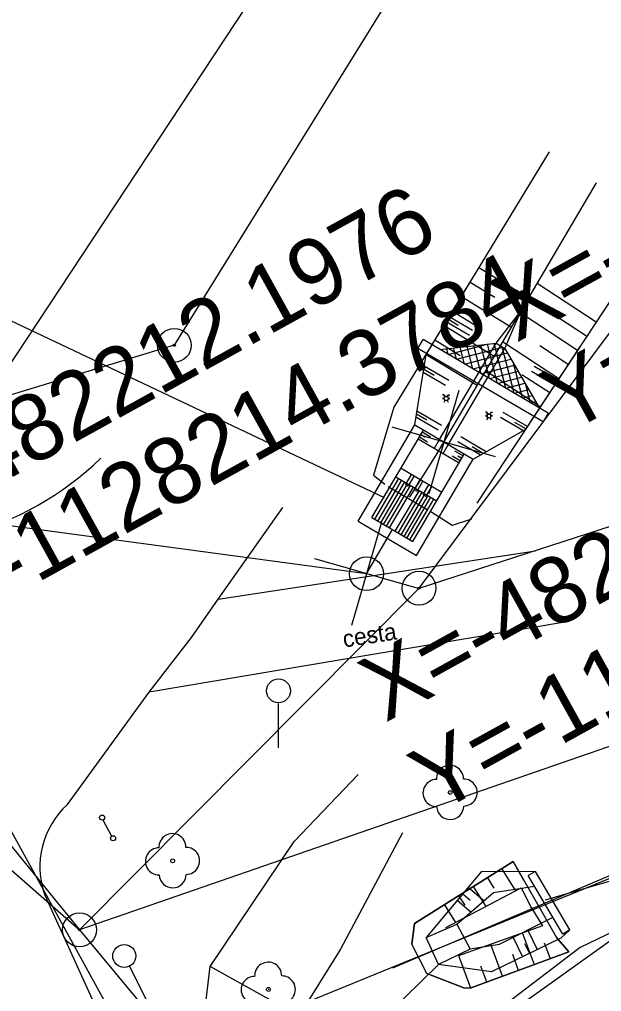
# Model space of a CAD drawing. Extents: x -483721 to -481876, y -1129170 to -1127366.
# Drawn here: x -482206.61 to -482189.41, y -1128228.85 to -1128200.12 of the extents above; entities that cross this region are included whole.
import ezdxf

# ---------------------------------------------------------------- set-up
doc = ezdxf.new("R2010")
doc.units = 0
for name, color, linetype in [('Hranice parcel', 7, 'Continuous'), ('kresba', 7, 'Continuous'), ('SO 01', 7, 'Continuous'), ('STROM', 7, 'Continuous'), ('u_HV', 7, 'Continuous'), ('u_vytyčení', 7, 'Continuous'), ('vzorák', 7, 'Continuous'), ('Značky bodu BP', 7, 'Continuous'), ('ˇ12', 7, 'Continuous'), ('ˇ8', 7, 'Continuous')]:
    doc.layers.add(name, color=color, linetype=linetype)

# ---------------------------------------------------------------- blocks, each defined once
blk = doc.blocks.new('STROM')
blk.add_circle((0, 0), 0.143)
for centre, start, end in [((-0.019, 1.012), 359.33392, 182.80997), ((-1.012, -0.037), 90.28964, 270.7727), ((0.994, 0), 270.35705, 90.71965), ((-1.012, -0.037), 2.55394, 2.80997), ((-0.019, 1.012), 270.28964, 270.71965), ((0, -0.993), 90.35705, 90.7727), ((0.994, 0), 179.33392, 179.58937), ((0, -0.993), 182.55394, 359.58937)]:
    blk.add_arc(centre, 1, start, end)

msp = doc.modelspace()

# ---------------------------------------------------------------- linework, layer by layer
at = {"layer": 'Hranice parcel'}
for p, q in [((-482132.99, -1128202.16), (-482204.83, -1128227.03)), ((-482194.8, -1128216.93), (-482167.83, -1128208.16)), ((-482204.83, -1128227.03), (-482194.8, -1128216.93)), ((-482213.95, -1128219.04), (-482204.83, -1128227.03)), ((-482198.83, -1128234.26), (-482186.92, -1128225.75)), ((-482204.83, -1128227.03), (-482198.83, -1128234.26))]:
    msp.add_line(p, q, dxfattribs=at)
for points in [[(-482194.8, -1128216.93), (-482149.76, -1128156.56), (-482131.701, -1128127.511)], [(-482164.86, -1128146.61), (-482163.44, -1128147.46), (-482202.03, -1128209.75), (-482210.32, -1128212.27)], [(-482228.12, -1128175.02), (-482207.37, -1128211.05), (-482169.26, -1128153.28)], [(-482214.43, -1128213.98), (-482210.05, -1128220.62), (-482205.48, -1128226.23), (-482204.83, -1128227.03)]]:
    msp.add_lwpolyline(points, dxfattribs=at)
at = {"layer": 'kresba'}
for p, q in [((-482200.73, -1128217.25), (-482198.82, -1128214.544)), ((-482200.73, -1128217.25), (-482191.36, -1128215.83)), ((-482201.52, -1128218.39), (-482200.73, -1128217.25)), ((-482190.49, -1128217.93), (-482202.77, -1128220)), ((-482202.77, -1128220), (-482201.52, -1128218.39)), ((-482205.19, -1128223.32), (-482202.77, -1128220)), ((-482198.95, -1128221.65), (-482198.95, -1128220.336)), ((-482198.49, -1128224.42), (-482196.6, -1128222.44)), ((-482204.138, -1128223.781), (-482203.882, -1128224.259)), ((-482195.29, -1128224.16), (-482197.12, -1128227.6)), ((-482200.97, -1128228.11), (-482198.49, -1128224.42)), ((-482187.18, -1128225.01), (-482191.07, -1128226.15)), ((-482184.556, -1128224.904), (-482190.04, -1128227.55)), ((-482192.96, -1128225.31), (-482194.59, -1128227.25)), ((-482191.36, -1128225.3), (-482192.96, -1128225.31)), ((-482191.36, -1128225.3), (-482191.575, -1128225.427)), ((-482190.34, -1128227.03), (-482191.36, -1128225.3)), ((-482190.555, -1128227.157), (-482191.575, -1128225.427)), ((-482192.885, -1128226.168), (-482193.352, -1128225.776)), ((-482192.6, -1128225.92), (-482191.393, -1128225.736)), ((-482205.86, -1128226), (-482203.7, -1128230.73)), ((-482193.68, -1128226.86), (-482192.6, -1128225.92)), ((-482193.272, -1128226.505), (-482193.678, -1128226.164)), ((-482193.285, -1128226.161), (-482193.513, -1128225.969)), ((-482190.846, -1128226.665), (-482192.43, -1128227.46)), ((-482194.59, -1128227.25), (-482193.68, -1128226.86)), ((-482193.68, -1128226.86), (-482193.29, -1128227.6)), ((-482191.588, -1128227.037), (-482191.308, -1128227.611)), ((-482190.34, -1128227.03), (-482190.61, -1128227.27)), ((-482190.34, -1128227.03), (-482190.555, -1128227.157)), ((-482194.226, -1128228.049), (-482194.59, -1128227.25)), ((-482190.61, -1128227.27), (-482192.66, -1128228.27)), ((-482192.022, -1128227.255), (-482191.744, -1128227.823)), ((-482190.04, -1128227.55), (-482198.56, -1128234.04)), ((-482197.12, -1128227.6), (-482198.35, -1128229.57)), ((-482193.29, -1128227.6), (-482194.226, -1128228.049)), ((-482192.43, -1128227.46), (-482193.29, -1128227.6)), ((-482191.68, -1128227.434), (-482191.539, -1128227.723)), ((-482203.352, -1128228.1), (-482202.46, -1128229.9)), ((-482201.28, -1128230.72), (-482200.97, -1128228.11)), ((-482198.35, -1128229.57), (-482200.97, -1128228.11)), ((-482196.73, -1128230.5), (-482194.226, -1128228.049)), ((-482192.66, -1128228.27), (-482194.226, -1128228.049))]:
    msp.add_line(p, q, dxfattribs=at)
for centre, radius in [((-482198.953, -1128219.963), 0.352), ((-482204.166, -1128223.711), 0.0752), ((-482203.841, -1128224.323), 0.0752), ((-482203.51, -1128227.8), 0.339)]:
    msp.add_circle(centre, radius, dxfattribs=at)
for centre, radius, start, end in [((-482210.645, -1128206.389), 9.298, 284.9928, 313.8842), ((-482203.498, -1128225.167), 2.504, 132.4901, 199.4374)]:
    msp.add_arc(centre, radius, start, end, dxfattribs=at)
at = {"layer": 'SO 01'}
for p, q in [((-482196.353, -1128216.503), (-482212.198, -1128214.378)), ((-482196.353, -1128216.503), (-482195.583, -1128215.192)), ((-482202.984, -1128231.154), (-482187.403, -1128224.778))]:
    msp.add_line(p, q, dxfattribs=at)
msp.add_lwpolyline([(-482202.984, -1128231.154), (-482212.198, -1128214.378), (-482227.058, -1128219.745), (-482256.094, -1128201.089), (-482297.311, -1128248.318), (-482304.782, -1128247.098), (-482364.54, -1128258.181), (-482368.011, -1128257.278)], dxfattribs=at)
msp.add_circle((-482196.353, -1128216.503), 0.5, dxfattribs=at)
at = {"layer": 'u_HV'}
for p, q in [((-482211.798, -1128206.696), (-482195.827, -1128214.245)), ((-482193.91, -1128208.898), (-482193.218, -1128209.304)), ((-482193.91, -1128208.898), (-482193.218, -1128209.304)), ((-482193.91, -1128208.898), (-482193.218, -1128209.304)), ((-482192.525, -1128209.69), (-482191.797, -1128208.739)), ((-482192.266, -1128209.842), (-482191.797, -1128208.739)), ((-482193.998, -1128209.044), (-482193.309, -1128209.448)), ((-482193.998, -1128209.044), (-482193.309, -1128209.448)), ((-482193.998, -1128209.044), (-482193.309, -1128209.448)), ((-482193.954, -1128208.971), (-482193.645, -1128209.153)), ((-482193.954, -1128208.971), (-482193.645, -1128209.153)), ((-482193.954, -1128208.971), (-482193.645, -1128209.153)), ((-482194.196, -1128212.536), (-482192.525, -1128209.69)), ((-482193.94, -1128210.019), (-482192.791, -1128209.72)), ((-482193.696, -1128210.162), (-482192.328, -1128209.806)), ((-482193.452, -1128210.305), (-482193.582, -1128209.808)), ((-482193.209, -1128210.448), (-482193.381, -1128209.786)), ((-482192.965, -1128210.592), (-482193.18, -1128209.763)), ((-482192.721, -1128210.735), (-482192.979, -1128209.741)), ((-482192.477, -1128210.878), (-482192.778, -1128209.719)), ((-482192.233, -1128211.022), (-482192.577, -1128209.696)), ((-482191.989, -1128211.165), (-482192.345, -1128209.796)), ((-482194.184, -1128209.875), (-482194.184, -1128209.875)), ((-482194.184, -1128209.875), (-482194.184, -1128209.875)), ((-482193.94, -1128210.019), (-482193.983, -1128209.853)), ((-482193.938, -1128212.688), (-482192.266, -1128209.842)), ((-482193.696, -1128210.162), (-482193.782, -1128209.831)), ((-482193.452, -1128210.305), (-482192.188, -1128209.977)), ((-482194.645, -1128210.361), (-482193.924, -1128210.785)), ((-482193.209, -1128210.448), (-482192.083, -1128210.156)), ((-482192.965, -1128210.592), (-482191.979, -1128210.336)), ((-482191.745, -1128211.308), (-482192.014, -1128210.276)), ((-482190.703, -1128210.782), (-482191.395, -1128210.375)), ((-482194.675, -1128210.541), (-482194.015, -1128210.928)), ((-482194.66, -1128210.451), (-482194.351, -1128210.633)), ((-482192.721, -1128210.735), (-482191.874, -1128210.515)), ((-482190.792, -1128210.927), (-482191.476, -1128210.525)), ((-482190.792, -1128210.927), (-482191.476, -1128210.525)), ((-482190.792, -1128210.927), (-482191.476, -1128210.525)), ((-482190.746, -1128210.856), (-482191.055, -1128210.674)), ((-482190.746, -1128210.856), (-482191.055, -1128210.674)), ((-482190.746, -1128210.856), (-482191.055, -1128210.674)), ((-482192.477, -1128210.878), (-482191.77, -1128210.695)), ((-482192.233, -1128211.022), (-482191.665, -1128210.874)), ((-482191.502, -1128211.451), (-482191.641, -1128210.916)), ((-482194.067, -1128211.211), (-482194.102, -1128211.211)), ((-482193.928, -1128211.211), (-482193.894, -1128211.211)), ((-482191.989, -1128211.165), (-482191.561, -1128211.054)), ((-482191.989, -1128211.165), (-482191.561, -1128211.054)), ((-482191.989, -1128211.165), (-482191.561, -1128211.054)), ((-482191.745, -1128211.308), (-482191.456, -1128211.233)), ((-482191.502, -1128211.451), (-482191.351, -1128211.412)), ((-482194.876, -1128211.777), (-482194.566, -1128211.958)), ((-482194.861, -1128211.686), (-482194.139, -1128212.11)), ((-482192.805, -1128211.728), (-482192.84, -1128211.728)), ((-482192.666, -1128211.728), (-482192.631, -1128211.728)), ((-482191.598, -1128212.152), (-482192.31, -1128211.733)), ((-482191.258, -1128211.595), (-482191.268, -1128211.556)), ((-482191.258, -1128211.595), (-482191.247, -1128211.592)), ((-482196.601, -1128214.95), (-482194.929, -1128212.105)), ((-482194.929, -1128212.105), (-482193.205, -1128213.118)), ((-482194.89, -1128211.867), (-482194.231, -1128212.254)), ((-482191.732, -1128212.27), (-482192.392, -1128211.882)), ((-482191.645, -1128212.223), (-482191.97, -1128212.032)), ((-482196.19, -1128214.844), (-482194.671, -1128212.257)), ((-482194.747, -1128212.386), (-482194.688, -1128212.421)), ((-482194.747, -1128212.386), (-482194.631, -1128212.455)), ((-482194.703, -1128212.313), (-482194.462, -1128212.455)), ((-482194.823, -1128212.516), (-482193.616, -1128213.225)), ((-482194.79, -1128212.46), (-482194.548, -1128212.602)), ((-482194.348, -1128212.794), (-482194.196, -1128212.536)), ((-482194.09, -1128212.946), (-482193.938, -1128212.688)), ((-482192.99, -1128212.992), (-482193.649, -1128212.604)), ((-482192.817, -1128212.896), (-482193.568, -1128212.455)), ((-482194.983, -1128215.553), (-482193.464, -1128212.966)), ((-482193.496, -1128213.022), (-482193.738, -1128212.88)), ((-482192.902, -1128212.945), (-482193.228, -1128212.754)), ((-482194.877, -1128215.963), (-482193.205, -1128213.118)), ((-482193.583, -1128213.169), (-482193.825, -1128213.027)), ((-482193.54, -1128213.096), (-482193.656, -1128213.027)), ((-482193.54, -1128213.096), (-482193.598, -1128213.061)), ((-482195.329, -1128213.378), (-482194.122, -1128214.087)), ((-482195.027, -1128213.555), (-482195.204, -1128213.856)), ((-482196.104, -1128214.894), (-482195.395, -1128213.687)), ((-482196.018, -1128214.945), (-482195.309, -1128213.738)), ((-482195.932, -1128214.996), (-482195.223, -1128213.789)), ((-482195.846, -1128215.046), (-482195.136, -1128213.839)), ((-482195.481, -1128213.637), (-482194.274, -1128214.346)), ((-482194.941, -1128213.606), (-482195.118, -1128213.907)), ((-482194.769, -1128213.707), (-482194.945, -1128214.008)), ((-482194.683, -1128213.758), (-482194.859, -1128214.059)), ((-482195.759, -1128215.097), (-482195.05, -1128213.89)), ((-482195.673, -1128215.148), (-482194.964, -1128213.94)), ((-482195.501, -1128215.249), (-482194.791, -1128214.042)), ((-482195.414, -1128215.3), (-482194.705, -1128214.092)), ((-482195.204, -1128213.856), (-482195.118, -1128213.907)), ((-482194.945, -1128214.008), (-482194.859, -1128214.059)), ((-482194.51, -1128213.859), (-482194.687, -1128214.16)), ((-482194.424, -1128213.91), (-482194.601, -1128214.21)), ((-482195.328, -1128215.35), (-482194.619, -1128214.143)), ((-482195.242, -1128215.401), (-482194.533, -1128214.194)), ((-482195.156, -1128215.452), (-482194.447, -1128214.244)), ((-482195.07, -1128215.502), (-482194.36, -1128214.295)), ((-482194.687, -1128214.16), (-482194.601, -1128214.21)), ((-482196.601, -1128214.95), (-482194.877, -1128215.963)), ((-482196.19, -1128214.844), (-482194.983, -1128215.553)), ((-482195.577, -1128228.156), (-482183.036, -1128222.814))]:
    msp.add_line(p, q, dxfattribs=at)
for points in [[(-482194.929, -1128212.105), (-482194.59, -1128210.02), (-482193.311, -1128207.91)], [(-482194.184, -1128209.875), (-482192.525, -1128209.69), (-482192.266, -1128209.842), (-482191.239, -1128211.606)], [(-482194.184, -1128209.875), (-482192.525, -1128209.69), (-482192.266, -1128209.842), (-482191.239, -1128211.606)], [(-482194.184, -1128209.875), (-482192.525, -1128209.69), (-482192.266, -1128209.842), (-482191.239, -1128211.606)], [(-482193.205, -1128213.118), (-482191.647, -1128212.226), (-482190.034, -1128209.775)], [(-482193.963, -1128211.268), (-482194.033, -1128211.268), (-482194.067, -1128211.211)], [(-482194.067, -1128211.211), (-482194.033, -1128211.268), (-482194.067, -1128211.324)], [(-482193.894, -1128211.324), (-482193.928, -1128211.324), (-482193.963, -1128211.268), (-482193.928, -1128211.211)], [(-482193.928, -1128211.211), (-482193.963, -1128211.268)], [(-482194.067, -1128211.324), (-482194.102, -1128211.324)], [(-482194.102, -1128211.324), (-482194.067, -1128211.324), (-482194.033, -1128211.38), (-482194.067, -1128211.437)], [(-482193.963, -1128211.38), (-482194.033, -1128211.38), (-482194.067, -1128211.324), (-482194.033, -1128211.268), (-482193.963, -1128211.268), (-482193.928, -1128211.324), (-482193.963, -1128211.38)], [(-482193.928, -1128211.437), (-482193.963, -1128211.38), (-482193.928, -1128211.324), (-482193.894, -1128211.324)], [(-482192.701, -1128211.784), (-482192.77, -1128211.784), (-482192.805, -1128211.728)], [(-482192.805, -1128211.728), (-482192.77, -1128211.784), (-482192.805, -1128211.84)], [(-482192.701, -1128211.896), (-482192.77, -1128211.897), (-482192.805, -1128211.84), (-482192.77, -1128211.784), (-482192.701, -1128211.784), (-482192.666, -1128211.84), (-482192.701, -1128211.896)], [(-482192.631, -1128211.84), (-482192.666, -1128211.84), (-482192.701, -1128211.784), (-482192.666, -1128211.728)], [(-482192.666, -1128211.728), (-482192.701, -1128211.784)], [(-482192.805, -1128211.84), (-482192.84, -1128211.84)], [(-482192.84, -1128211.84), (-482192.805, -1128211.84), (-482192.77, -1128211.897), (-482192.805, -1128211.953)], [(-482192.666, -1128211.953), (-482192.701, -1128211.896), (-482192.666, -1128211.84), (-482192.631, -1128211.84)]]:
    msp.add_lwpolyline(points, dxfattribs=at)
for points in [[(-482192.02, -1128225.01), (-482190.74, -1128227.25), (-482190.37, -1128227.68), (-482193.29, -1128228.75), (-482193.48, -1128228.74), (-482194.57, -1128228.32), (-482195.01, -1128227.45), (-482194.93, -1128226.84)], [(-482194.93, -1128226.84), (-482192.02, -1128225.01), (-482190.74, -1128227.25), (-482190.37, -1128227.68), (-482193.29, -1128228.75), (-482193.48, -1128228.74), (-482194.57, -1128228.32), (-482195.01, -1128227.45)]]:
    msp.add_lwpolyline(points, close=True, dxfattribs=at)
at = {"layer": 'u_vytyčení'}
for p, q in [((-482193.627, -1128211.083), (-482194.507, -1128214.141)), ((-482192.538, -1128213.051), (-482195.596, -1128212.172)), ((-482195.913, -1128214.974), (-482196.793, -1128218.032)), ((-482194.824, -1128216.943), (-482197.882, -1128216.063))]:
    msp.add_line(p, q, dxfattribs=at)
at = {"layer": 'vzorák'}
for p, q in [((-482194.833, -1128209.842), (-482194.681, -1128209.583)), ((-482190.98, -1128211.758), (-482194.681, -1128209.583)), ((-482191.132, -1128212.017), (-482194.833, -1128209.842)), ((-482190.98, -1128211.758), (-482191.131, -1128212.015))]:
    msp.add_line(p, q, dxfattribs=at)
at = {"layer": 'Značky bodu BP'}
for centre, radius in [((-482202.03, -1128209.75), 0.5), ((-482202.03, -1128209.75), 0.0303), ((-482194.8, -1128216.93), 0.5), ((-482194.8, -1128216.93), 0.0303), ((-482204.83, -1128227.03), 0.5), ((-482204.83, -1128227.03), 0.0303)]:
    msp.add_circle(centre, radius, dxfattribs=at)
at = {"layer": 'ˇ12'}
for p, q in [((-482190.96, -1128204.03), (-482195.54, -1128211.58)), ((-482189.57, -1128204.95), (-482194.3, -1128213)), ((-482187.61, -1128206.09), (-482193.09, -1128214.42)), ((-482193.03, -1128207.45), (-482191.56, -1128208.35)), ((-482193.29, -1128207.88), (-482192.56, -1128208.33)), ((-482189.57, -1128209.07), (-482191.31, -1128207.92)), ((-482193.55, -1128208.31), (-482192.07, -1128209.21)), ((-482193.81, -1128208.74), (-482193.07, -1128209.19)), ((-482190.12, -1128209.9), (-482191.82, -1128208.78)), ((-482189.85, -1128209.48), (-482190.71, -1128208.92)), ((-482194.07, -1128209.16), (-482192.58, -1128210.07)), ((-482194.33, -1128209.59), (-482193.58, -1128210.05)), ((-482190.67, -1128210.74), (-482192.33, -1128209.65)), ((-482190.39, -1128210.32), (-482191.23, -1128209.77)), ((-482194.59, -1128210.02), (-482193.08, -1128210.93)), ((-482191.22, -1128211.57), (-482192.84, -1128210.51)), ((-482190.94, -1128211.16), (-482191.76, -1128210.62)), ((-482195.54, -1128211.58), (-482196.15, -1128213.59)), ((-482194.3, -1128213), (-482195.07, -1128214.22)), ((-482196.15, -1128213.59), (-482195.81, -1128213.86)), ((-482195.07, -1128214.22), (-482195.09, -1128214.24)), ((-482193.82, -1128215.08), (-482194.45, -1128214.67)), ((-482193.25, -1128214.89), (-482193.82, -1128215.08)), ((-482192.02, -1128225.01), (-482194.93, -1128226.84)), ((-482191.7, -1128225.57), (-482192.02, -1128225.01)), ((-482192.36, -1128225.22), (-482191.95, -1128225.88)), ((-482192.78, -1128225.49), (-482192.59, -1128225.8)), ((-482194.01, -1128226.96), (-482191.78, -1128225.79)), ((-482193.2, -1128225.75), (-482192.83, -1128226.34)), ((-482191.78, -1128225.79), (-482191.49, -1128226.37)), ((-482193.63, -1128226.02), (-482193.45, -1128226.3)), ((-482194.05, -1128226.29), (-482193.72, -1128226.81)), ((-482191.49, -1128226.37), (-482191.15, -1128226.91)), ((-482194.93, -1128226.84), (-482195.01, -1128227.45)), ((-482191.15, -1128226.91), (-482193.63, -1128227.8)), ((-482191.39, -1128228.06), (-482191.74, -1128227.12)), ((-482190.37, -1128227.68), (-482190.74, -1128227.25)), ((-482192.33, -1128228.4), (-482192.68, -1128227.46)), ((-482190.92, -1128227.89), (-482191.09, -1128227.42)), ((-482193.27, -1128228.75), (-482193.62, -1128227.8)), ((-482193.29, -1128228.75), (-482190.37, -1128227.68)), ((-482191.86, -1128228.23), (-482192.03, -1128227.76)), ((-482192.8, -1128228.58), (-482192.97, -1128228.1)), ((-482194.57, -1128228.32), (-482193.48, -1128228.74)), ((-482193.48, -1128228.74), (-482193.29, -1128228.75))]:
    msp.add_line(p, q, dxfattribs=at)
at = {"layer": 'ˇ8'}
msp.add_line((-482194.56, -1128214.61), (-482195.71, -1128213.93), dxfattribs=at)

# ---------------------------------------------------------------- block references
at = {"layer": 'STROM'}
for p, xscale, yscale in [((-482193.88, -1128222.97), 0.4000000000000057, 0.4000000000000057), ((-482202.08, -1128224.99), 0.3999999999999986, 0.3999999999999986), ((-482199.25, -1128228.79), 0.3999999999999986, 0.3999999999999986)]:
    msp.add_blockref('STROM', p, dxfattribs=dict(at, xscale=xscale, yscale=yscale))

# ---------------------------------------------------------------- texts
at = {"layer": 'kresba'}
msp.add_text('cesta', height=0.5, rotation=8.7405, dxfattribs=at).set_placement((-482197.015, -1128218.684))
at = {"layer": 'u_vytyčení'}
for s, p in [('X=-482194.0671', (-482191.927, -1128209.681)), ('Y=-1128212.6117', (-482190.429, -1128212.388)), ('X=-482212.1976', (-482211.244, -1128216.101)), ('Y=-1128214.3784', (-482209.747, -1128218.808)), ('X=-482196.3528', (-482195.794, -1128220.912)), ('Y=-1128216.5033', (-482194.296, -1128223.619))]:
    msp.add_text(s, height=1.96875, rotation=28.9559, dxfattribs=at).set_placement(p)

doc.saveas('drawing.dxf')
